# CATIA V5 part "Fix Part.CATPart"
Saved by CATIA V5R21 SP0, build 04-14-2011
Part number: Part4
Bounding box of the stored display mesh (mm): x -100 to 100, y -30 to 50, z -10 to 111
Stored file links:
  D:\CATIA V5R21 E-RESOURCES\CATIA-V5R21\catia-v5r21-Prts\c16_catia_v5r21_prt\Rack Joint-(Fig16-57)\Fix Part.CATPart
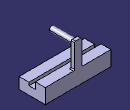
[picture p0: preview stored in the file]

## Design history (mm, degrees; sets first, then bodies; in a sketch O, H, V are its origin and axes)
Body1 (main body)
  Sketch1 on yz-plane, origin (0, 0, 0), H (0, 1, 0), V (0, 0, 1)
    line L1 (50, 35) -> (50, -10)
    line L2 (50, -10) -> (-30, -10)
    line L3 (0, 15) -> (20, 15)
    line L4 (20, 15) -> (20, 35)
    point P5 (0, 15)
    reference intersected line E1 through (0, 0) direction (-1, 0) from xy-plane
    reference intersected line E3 through (0, 0) direction (0, 1) from zx-plane
    line L5 (20, 35) -> (50, 35)
    reference intersected line E4 through (0, 0) direction (-1, 0) from xy-plane
    reference intersected line E6 through (0, 0) direction (0, 1) from zx-plane
    line L6 (0, 15) -> (0, 24)
    line L7 (0, 24) -> (-30, 24)
    line L8 (-30, 24) -> (-30, -10)
    distance H L2 = 10
    distance V L1 = 50
    distance E1 L3 = 15
    length L6 = 9
    length L4 = 20
    length L3 = 20
    length L2 = 80
    vertical: L1 V, L4 V, E3 V, E6 V, L6 V, L8 V
    horizontal: L2 H, L3 H, E1 H, L5 H, E4 H, L7 H
    perpendicularity: E1 L1
    coincidence: P5 V
  Pad1: profile Sketch1, direction (1, 0, 0), length 100, mirrored extent
  Sketch2 on face of Pad1 from Sketch1.L1, origin (0, 50, 0), H (-1, 0, 0), V (0, 0, 1)
    circle A1 centre (0, 100) radius 7.5
    point P1 (0, 100)
    radius A1 = 7.5
    distance H P1 = 100
    coincidence: P1 V
  Pad2: profile Sketch2, direction (0, -1, 0), up to face of Pad1 from Sketch1.L8
  Sketch3 on face of Pad1 from Sketch1.L1, origin (0, 50, 0), H (-1, 0, 0), V (0, 0, 1)
    line L1 (-11, 111) -> (11, 111)
    line L2 (11, 111) -> (11, -10)
    line L3 (11, -10) -> (-11, -10)
    line L4 (-11, -10) -> (-11, 111)
    length L3 = 22
    distance V L2 = 11
    distance L1 L3 = 121
    distance L3 H = 10
    horizontal: L1 H, L3 H
    vertical: L2 V, L4 V
  Pad3: profile Sketch3, direction (0, -1, 0), length 10
  Fillet1: radius 3, on edge [end face of Pad3 | face of Pad1 from Sketch1.L5]; edge [face of Pad3 from Sketch3.L4 | face of Pad1 from Sketch1.L5]; edge [face of Pad1 from Sketch1.L5 | face of Pad3 from Sketch3.L2]; edge [face of Pad2 from Sketch2.A1 | end face of Pad3]; edge [face of Pad3 from Sketch3.L1 | face of Pad3 from Sketch3.L4]; edge [face of Pad3 from Sketch3.L2 | face of Pad3 from Sketch3.L1]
